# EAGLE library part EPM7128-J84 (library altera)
EPM70128 MAX 7000 family
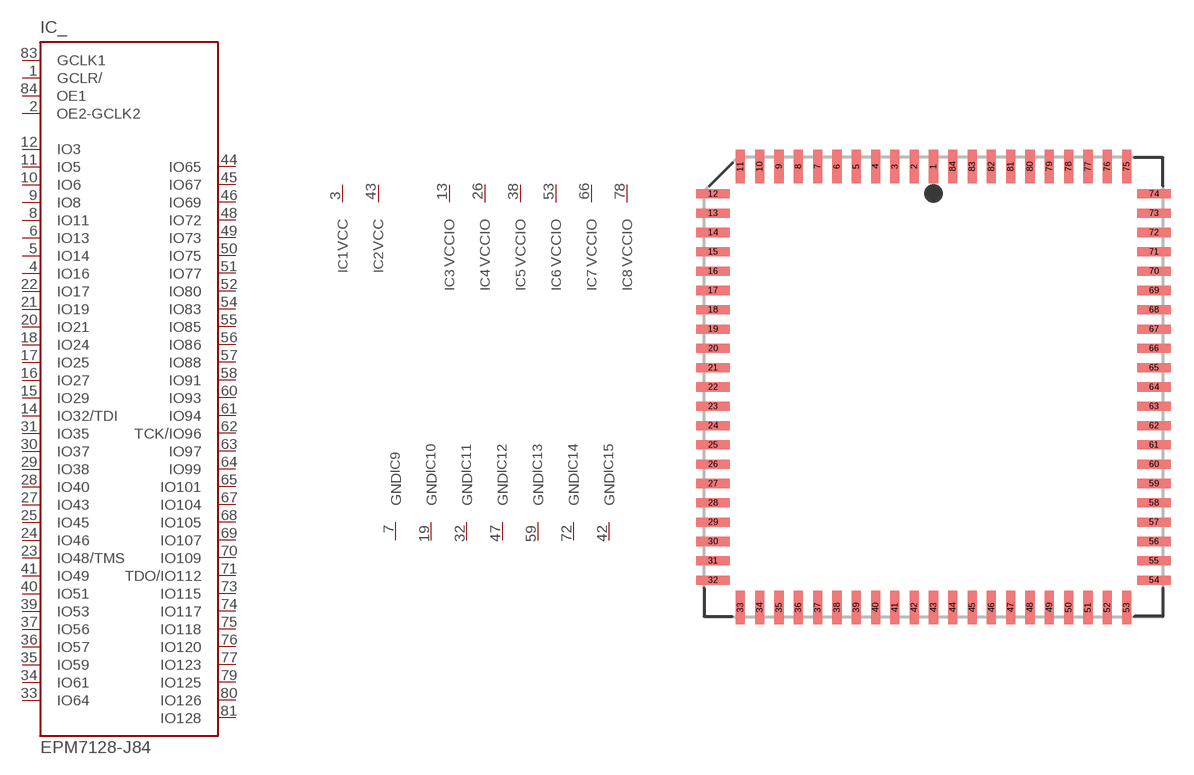
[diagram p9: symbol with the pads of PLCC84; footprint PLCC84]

Designator prefix IC; gates _=7128-84 1=VCC 2=VCC 3=VCCIO 4=VCCIO 5=VCCIO 6=VCCIO 7=VCCIO 8=VCCIO 9=GND 10=GND 11=GND 12=GND 13=GND 14=GND 15=GND 16=GND

## EPM7128-J84 (MPN: EPM7128SLC84-7N; OC_FARNELL: 1549458; OC_NEWARK: 51R9744)  [PLCC84]
1  _:GCLR/  in
2  _:OE2-GCLK2  in
3  1:VCC  pwr
4  _:IO16
5  _:IO14
6  _:IO13
7  9:GND  pwr
8  _:IO11
9  _:IO8
10  _:IO6
11  _:IO5
12  _:IO3
13  3:VCCIO  pwr
14  _:IO32/TDI
15  _:IO29
16  _:IO27
17  _:IO25
18  _:IO24
19  10:GND  pwr
20  _:IO21
21  _:IO19
22  _:IO17
23  _:IO48/TMS
24  _:IO46
25  _:IO45
26  4:VCCIO  pwr
27  _:IO43
28  _:IO40
29  _:IO38
30  _:IO37
31  _:IO35
32  11:GND  pwr
33  _:IO64
34  _:IO61
35  _:IO59
36  _:IO57
37  _:IO56
38  5:VCCIO  pwr
39  _:IO53
40  _:IO51
41  _:IO49
42  15:GND  pwr
43  2:VCC  pwr
44  _:IO65
45  _:IO67
46  _:IO69
47  12:GND  pwr
48  _:IO72
49  _:IO73
50  _:IO75
51  _:IO77
52  _:IO80
53  6:VCCIO  pwr
54  _:IO83
55  _:IO85
56  _:IO86
57  _:IO88
58  _:IO91
59  13:GND  pwr
60  _:IO93
61  _:IO94
62  _:TCK/IO96
63  _:IO97
64  _:IO99
65  _:IO101
66  7:VCCIO  pwr
67  _:IO104
68  _:IO105
69  _:IO107
70  _:IO109
71  _:TDO/IO112
72  14:GND  pwr
73  _:IO115
74  _:IO117
75  _:IO118
76  _:IO120
77  _:IO123
78  8:VCCIO  pwr
79  _:IO125
80  _:IO126
81  _:IO128
82  16:GND  pwr
83  _:GCLK1  in
84  _:OE1  in

## Footprint PLCC84 (pad centres in mm)
Plastic J-Lead Chip Carrier
smd 0.6 x 2.2: 1 0,14.5; 2 -1.27,14.5; 3 -2.54,14.5; 4 -3.81,14.5; 5 -5.08,14.5; 6 -6.35,14.5; 7 -7.62,14.5; 8 -8.89,14.5; 9 -10.16,14.5; 10 -11.43,14.5; 11 -12.7,14.5; 33 -12.7,-14.5; 34 -11.43,-14.5; 35 -10.16,-14.5; 36 -8.89,-14.5; 37 -7.62,-14.5; 38 -6.35,-14.5; 39 -5.08,-14.5; 40 -3.81,-14.5; 41 -2.54,-14.5; 42 -1.27,-14.5; 43 0,-14.5; 44 1.27,-14.5; 45 2.54,-14.5; 46 3.81,-14.5; 47 5.08,-14.5; 48 6.35,-14.5; 49 7.62,-14.5; 50 8.89,-14.5; 51 10.16,-14.5; 52 11.43,-14.5; 53 12.7,-14.5; 75 12.7,14.5; 76 11.43,14.5; 77 10.16,14.5; 78 8.89,14.5; 79 7.62,14.5; 80 6.35,14.5; 81 5.08,14.5; 82 3.81,14.5; 83 2.54,14.5; 84 1.27,14.5
smd 2.2 x 0.6: 12 -14.5,12.7; 13 -14.5,11.43; 14 -14.5,10.16; 15 -14.5,8.89; 16 -14.5,7.62; 17 -14.5,6.35; 18 -14.5,5.08; 19 -14.5,3.81; 20 -14.5,2.54; 21 -14.5,1.27; 22 -14.5,0; 23 -14.5,-1.27; 24 -14.5,-2.54; 25 -14.5,-3.81; 26 -14.5,-5.08; 27 -14.5,-6.35; 28 -14.5,-7.62; 29 -14.5,-8.89; 30 -14.5,-10.16; 31 -14.5,-11.43; 32 -14.5,-12.7; 54 14.5,-12.7; 55 14.5,-11.43; 56 14.5,-10.16; 57 14.5,-8.89; 58 14.5,-7.62; 59 14.5,-6.35; 60 14.5,-5.08; 61 14.5,-3.81; 62 14.5,-2.54; 63 14.5,-1.27; 64 14.5,0; 65 14.5,1.27; 66 14.5,2.54; 67 14.5,3.81; 68 14.5,5.08; 69 14.5,6.35; 70 14.5,7.62; 71 14.5,8.89; 72 14.5,10.16; 73 14.5,11.43; 74 14.5,12.7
